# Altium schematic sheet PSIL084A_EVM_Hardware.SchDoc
size 431 x 279 mm; Date: Not shown in title block; ApprovedBy: Not shown in title block; CheckedBy: Not shown in title block; Author: Not shown in title block; CompanyName: Not shown in title block; Engineer: Not shown in title block; Organization: Not shown in title block; Address1: Not shown in title block; Address2: Not shown in title block; Address3: Not shown in title block; Address4: Not shown in title block; DocumentNumber: 3; Revision: Use project parameter SCH_Rev; SheetNumber: 3; SheetTotal: 3; PageSetup: Record=PageOptions¦CenterHorizontal=True¦CenterVertical=True¦PrintScale=1.00¦XCorrection=1.00¦YCorrection=1.00¦PrintKind=0¦BorderSize=5000000¦LeftOffset=0¦BottomOffset=0¦Orientation=2¦PaperLength=1000¦PaperWidth=1000¦Scale=100¦PaperSource=15¦PrintQuality=600¦MediaType=1¦DitherType=10¦PaperKind=Letter¦PrintScaleMode=1
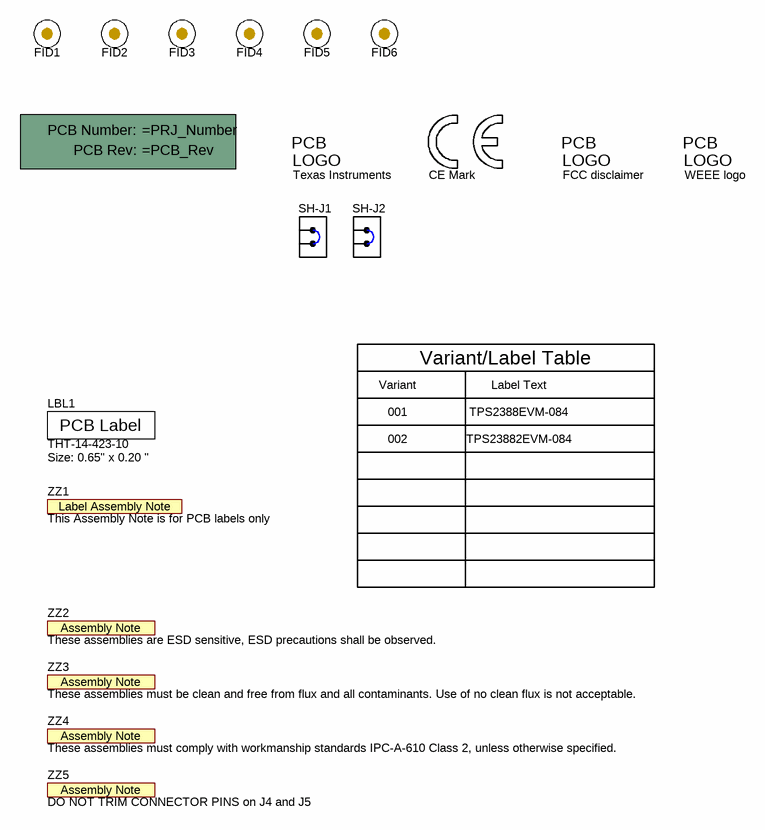
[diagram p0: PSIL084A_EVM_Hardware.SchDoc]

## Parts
!PCB  Printed Circuit Board  (value not drawn)  (mechanical)
FID1  Fiducial  [Fiducial10-20]  (value not drawn)
FID2  Fiducial  [Fiducial10-20]  (value not drawn)
FID3  Fiducial  [Fiducial10-20]  (value not drawn)
FID4  Fiducial  [Fiducial10-20]  (value not drawn)
FID5  Fiducial  [Fiducial10-20]  (value not drawn)
FID6  Fiducial  [Fiducial10-20]  (value not drawn)
LBL1  THT-14-423-10  Note: Size: 0.65" x 0.20 "  [Label_650x200]
Logo1  Texas Instruments  [TI_Stacked_Overlay_Small]  (no BOM)
Logo2  CE Mark  [CE_Mark_5mm]  (no BOM)
Logo3  FCC disclaimer  [FCC_disclaimer]  (no BOM)
Logo4  WEEE logo  [WEEE_Minimum]  (no BOM)
SH-J1  SPC02SYAN  [SPC02SYAN]  (value not drawn)
SH-J2  SPC02SYAN  [SPC02SYAN]  (value not drawn)
ZZ1  This Assembly Note is for PCB labels only  [AssemblyNoteLabel]  (no BOM)
ZZ2  These assemblies are ESD sensitive, ESD precautions shall be observed.  [AssemblyNote]  (no BOM)
ZZ3  These assemblies must be clean and free from flux and all contaminants. Use of no clean flux is not acceptable.  [AssemblyNote]  (no BOM)
ZZ4  These assemblies must comply with workmanship standards IPC-A-610 Class 2, unless otherwise specified.  [AssemblyNote]  (no BOM)
ZZ5  DO NOT TRIM CONNECTOR PINS on J4 and J5  [AssemblyNote]  (no BOM)

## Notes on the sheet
- Variant
- Variant/Label Table
- Label Text
- 001
- 002
- TPS2388EVM-084
- TPS23882EVM-084

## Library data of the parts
!PCB = CMP-0003618-2: Manufacturer: Any
FID1-FID6 = CMP-0077181-1: Fiducial mark.  There is nothing to buy or mount.
LBL1 = CMP-0003625-1: Thermal Transfer Printable Labels, 0.650" W x 0.200" H - 10,000 per roll; Manufacturer: Brady; CompType: Label
Logo1 = CMP-0074838-1: Texas Instrument Corporate Signature; SymbolCreator: a0412235; Lib Reference: TI_Logo; Library Reference: Logo
Logo2 = CMP-0074844-1: SymbolCreator: a0412235
Logo3 = CMP-0074847-1: FCC_disclaimer; Library Reference: Logo
Logo4 = CMP-0074769-1
SH-J1 SH-J2 = CMP-0003642-1: Shunt, 100mil, Flash Gold, Black; Manufacturer: Sullins Connector Solutions; Value: 1x2; Note: You can "mate" this to a header by matching the designator.  i.e. use SH-J3 for header J3
ZZ1 = CMP-0003616-3
ZZ2 = CMP-0077236-1
ZZ3 = CMP-0077237-1
ZZ4 = CMP-0077238-1
ZZ5 = CMP-0077238-1: DO NOT TRIM CONNECTOR PINS on J5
